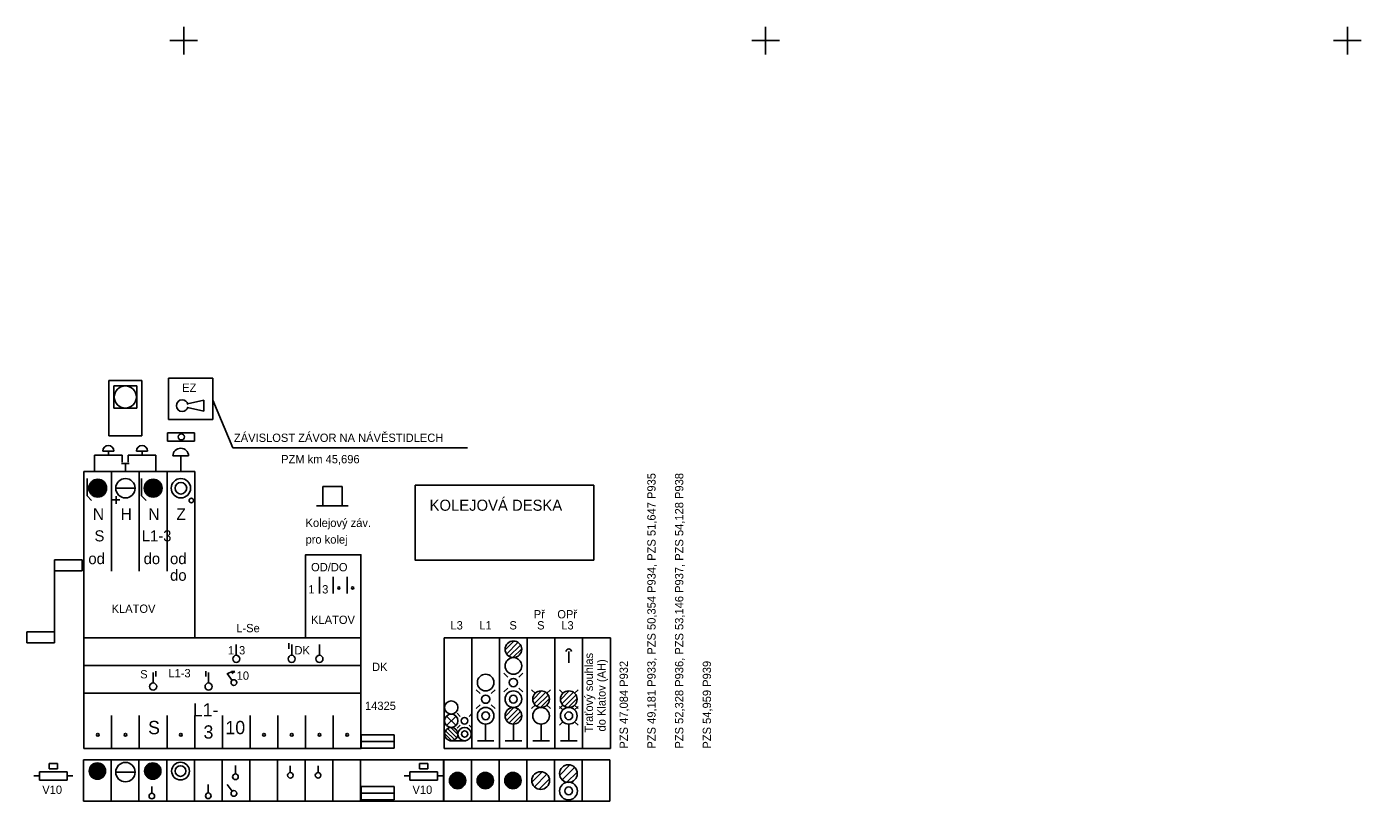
# Model space of a CAD drawing. Extents: x -28 to 822, y 61 to 665.
# Drawn here: x 340.1 to 821.8, y 385.1 to 664.7 of the extents above; entities that cross this region are included whole.
import ezdxf

# ---------------------------------------------------------------- set-up
doc = ezdxf.new("R2010")
doc.units = 0
for name, color, linetype in [('KOLEJIŠTĚ', 7, 'Continuous'), ('nové', 7, 'Continuous'), ('POPIS', 7, 'Continuous'), ('Vrstva 60', 7, 'Continuous')]:
    doc.layers.add(name, color=color, linetype=linetype)

# ---------------------------------------------------------------- blocks, each defined once
blk = doc.blocks.new('ZT18')
for p, q in [((10, 6), (0, 6)), ((0, 6), (0, 2)), ((10, 2), (10, 6)), ((0, 2), (10, 2))]:
    blk.add_line(p, q)
blk.add_lwpolyline([(0, 4), (0, 4), (10, 4)])
blk = doc.blocks.new('ZT95')
for p, q in [((2.79, 4.07), (0.93, 2.21)), ((3.63, 3.63), (1.37, 1.37)), ((4.07, 2.79), (2.21, 0.93))]:
    blk.add_line(p, q)
blk.add_circle((2.5, 2.5), 1.6)
blk = doc.blocks.new('HR6')
for p, q in [((-2.26, 0.4), (2.26, 0.4)), ((-2.2, 0.09), (2.2, 0.09)), ((-2.16, 0.8), (2.16, 0.8)), ((-1.96, 1.2), (1.96, 1.2)), ((-1.75, 1.49), (1.75, 1.49)), ((-1.56, 1.69), (1.56, 1.69)), ((-1.3, 1.89), (1.3, 1.89)), ((-0.95, 2.09), (0.95, 2.09)), ((-2.26, -0.4), (2.26, -0.4)), ((-2.2, -0.09), (2.2, -0.09)), ((-2.16, -0.8), (2.16, -0.8)), ((-1.96, -1.2), (1.96, -1.2)), ((-1.75, -1.49), (1.75, -1.49)), ((-1.56, -1.69), (1.56, -1.69)), ((-1.3, -1.89), (1.3, -1.89)), ((-0.95, -2.09), (0.95, -2.09))]:
    blk.add_line(p, q)
for start, end in [(0, 180), (180, 0)]:
    blk.add_arc((0, 0), 2.3, start, end)
blk = doc.blocks.new('ZT94')
at = {"xscale": 0.6400000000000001, "yscale": 0.6400000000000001}
blk.add_blockref('HR6', (2.5, 2.5), dxfattribs=at)
blk = doc.blocks.new('ZT87')
for start, end in [(0, 180), (180, 0)]:
    blk.add_arc((2.5, 2.5), 0.25, start, end)
blk = doc.blocks.new('ZT54')
for p, q in [((4.71, 6.11), (5.58, 5.6)), ((4.73, 6.09), (5.71, 6.11)), ((5.48, 3.64), (6.92, 5.56))]:
    blk.add_line(p, q)
blk.add_circle((5, 3), 0.8)
blk.add_arc((4.55, 1.46), 4.63, 60.0691, 87.3254)
blk = doc.blocks.new('HR1')
blk.add_line((-2.5, 0), (2.5, 0))
blk.add_circle((0, 0), 2.5)
blk = doc.blocks.new('ZT75')
at = {"xscale": 0.8, "yscale": 0.8000000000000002}
blk.add_blockref('HR6', (0, 0), dxfattribs=at)
blk = doc.blocks.new('HR3')
for radius in [2.5, 1.5]:
    blk.add_circle((0, 0), radius)
blk = doc.blocks.new('ZT72')
at = {"xscale": 0.8, "yscale": 0.8000000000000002}
blk.add_blockref('HR3', (0, 0), dxfattribs=at)
blk = doc.blocks.new('ZT41')
blk.add_line((5, 10.8), (5, 13.2))
blk.add_circle((5, 10), 0.8)
blk = doc.blocks.new('ZT11')
for p, q in [((-5, 7.5), (-5, 5.5)), ((-5, 7.5), (0, 7.5)), ((0, 7.5), (0, -7.5)), ((-5, 5.5), (0, 5.5)), ((5, -5.5), (0, -5.5)), ((5, -7.5), (5, -5.5)), ((0, -7.5), (5, -7.5))]:
    blk.add_line(p, q)
blk = doc.blocks.new('ZT44')
blk.add_line((5, 3.8), (5, 6.2))
blk.add_circle((5, 3), 0.8)
blk = doc.blocks.new('ZN4')
for p, q in [((-1, 0), (1, 0)), ((0, 1), (0, -1))]:
    blk.add_line(p, q)
blk = doc.blocks.new('ZT17')
for p, q in [((-2.5, 5), (2.5, 5)), ((-2.5, 0), (-2.5, 5)), ((2.5, 5), (2.5, 0)), ((-4.0625, 0), (4.0625, 0))]:
    blk.add_line(p, q)
blk = doc.blocks.new('HR')
for p, q in [((-3.54, 10.21), (-3.54, 0.21)), ((2.46, 10.21), (-3.54, 10.21)), ((2.46, 0.21), (2.46, 10.21)), ((-3.54, 0.21), (2.46, 0.21))]:
    blk.add_line(p, q)
blk.add_circle((-0.54, 7.21), 2)
at = {"layer": 'KOLEJIŠTĚ'}
for p, q in [((-2.59, 5.2), (-2.59, 9.25)), ((-2.59, 9.25), (1.51, 9.25)), ((1.51, 9.25), (1.51, 5.2)), ((1.51, 5.2), (-2.59, 5.2))]:
    blk.add_line(p, q, dxfattribs=at)
blk = doc.blocks.new('SB1')
for p, q in [((0, 1.08), (-1, 1.08)), ((1, 1.08), (0, 1.08)), ((0, 1.08), (0, -1.08))]:
    blk.add_line(p, q)
blk = doc.blocks.new('KD5')
for p, q in [((-2, 4), (2, 4)), ((0, 4), (0, 0))]:
    blk.add_line(p, q)
blk.add_arc((0, 4), 2, 0, 180)
blk = doc.blocks.new('ZT12')
blk.add_blockref('KD5', (0, 0))
blk = doc.blocks.new('KD15')
for p, q in [((-1.5, -6), (-0.5, -1.5)), ((0.5, -1.5), (1.5, -6)), ((-1.5, -6), (1.5, -6))]:
    blk.add_line(p, q)
for start, end in [(0, 180), (0, 180), (0, 180), (0, 180), (0, 180), (0, 180), (180, 257.0613), (282.9188, 360), (282.9188, 360), (282.9188, 360), (282.9188, 360), (282.9188, 360), (281.7695, 0)]:
    blk.add_arc((0, 0), 1.63, start, end)

msp = doc.modelspace()

# ---------------------------------------------------------------- linework, layer by layer
for p, q in [((371.62, 511.53), (367.62, 511.53)), ((369.62, 511.53), (369.62, 510.03)), ((379.78, 511.53), (383.78, 511.53)), ((381.78, 511.53), (381.78, 510.03)), ((374.62, 510.03), (364.62, 510.03)), ((364.62, 510.03), (364.62, 504.2)), ((374.62, 507.53), (374.62, 510.03)), ((376.78, 507.53), (376.78, 510.03)), ((376.78, 510.03), (386.78, 510.03)), ((386.78, 510.03), (386.78, 504.2)), ((361.92, 501.63), (361.92, 495.34)), ((381.61, 501.63), (381.61, 495.34)), ((361.92, 495.34), (363.55, 493.71)), ((381.61, 495.34), (383.23, 493.71)), ((515.98, 442.98), (512.78, 439.78)), ((517.38, 442.38), (513.38, 438.38)), ((518.38, 441.48), (514.18, 437.38)), ((518.78, 440.18), (515.58, 436.98)), ((535.78, 439.14), (535.78, 435.14)), ((513.78, 429.98), (512.38, 431.38)), ((517.78, 429.98), (519.18, 431.38)), ((503.78, 423.98), (502.38, 425.38)), ((507.78, 423.98), (509.18, 425.38)), ((513.78, 425.98), (512.38, 424.58)), ((517.78, 425.98), (519.18, 424.58)), ((523.78, 423.98), (522.38, 425.38)), ((525.98, 424.98), (522.78, 421.78)), ((527.38, 424.38), (523.38, 420.38)), ((527.78, 423.98), (529.18, 425.38)), ((533.78, 423.98), (532.38, 425.38)), ((535.98, 424.98), (532.78, 421.78)), ((537.38, 424.38), (533.38, 420.38)), ((537.78, 423.98), (539.18, 425.38)), ((503.78, 419.98), (502.38, 418.58)), ((507.78, 419.98), (509.18, 418.58)), ((523.78, 419.98), (522.38, 418.58)), ((528.38, 423.48), (524.18, 419.38)), ((528.78, 422.18), (525.58, 418.98)), ((527.78, 419.98), (529.18, 418.58)), ((533.78, 419.98), (532.38, 418.58)), ((533.78, 417.98), (532.38, 419.38)), ((538.38, 423.48), (534.18, 419.38)), ((538.78, 422.18), (535.58, 418.98)), ((537.78, 419.98), (539.18, 418.58)), ((537.78, 417.98), (539.18, 419.38)), ((494.98, 412.58), (491.78, 415.78)), ((494.98, 415.78), (491.78, 412.58)), ((496.58, 415.78), (495.46, 416.9)), ((499.78, 415.78), (500.9, 416.9)), ((515.98, 418.98), (512.78, 415.78)), ((517.38, 418.38), (513.38, 414.38)), ((518.38, 417.48), (514.18, 413.38)), ((518.78, 416.18), (515.58, 412.98)), ((490.98, 409.54), (493.54, 406.98)), ((491.3, 410.58), (494.66, 407.3)), ((492.1, 411.3), (495.3, 408.1)), ((493.22, 411.78), (495.78, 409.22)), ((496.58, 412.58), (495.46, 411.46)), ((499.78, 412.58), (500.9, 411.46)), ((505.78, 412.98), (505.78, 406.98)), ((515.78, 412.98), (515.78, 406.98)), ((525.78, 412.98), (525.78, 406.98)), ((533.78, 413.98), (532.38, 412.58)), ((535.78, 412.98), (535.78, 406.98)), ((537.78, 413.98), (539.18, 412.58)), ((492.78, 406.98), (498.78, 406.98)), ((502.78, 406.98), (508.78, 406.98)), ((512.78, 406.98), (518.78, 406.98)), ((522.78, 406.98), (528.78, 406.98)), ((532.78, 406.98), (538.78, 406.98)), ((360.62, 400.11), (360.62, 385.11)), ((460.62, 400.11), (460.62, 385.11)), ((490.62, 400.11), (490.62, 385.11)), ((354.76, 395.79), (344.76, 395.79)), ((344.76, 395.79), (344.76, 392.79)), ((354.76, 392.79), (354.76, 395.79)), ((435.28, 395.44), (435.28, 397.97)), ((445.28, 395.44), (445.28, 397.97)), ((478.37, 395.79), (478.37, 392.79)), ((488.37, 395.79), (478.37, 395.79)), ((488.37, 392.79), (488.37, 395.79)), ((342.76, 394.29), (344.76, 394.29)), ((344.76, 392.79), (354.76, 392.79)), ((354.76, 394.29), (356.76, 394.29)), ((385.28, 387.94), (385.28, 390.47)), ((414.31, 388.78), (412.47, 391.24)), ((476.37, 394.29), (478.37, 394.29)), ((478.37, 392.79), (488.37, 392.79)), ((488.37, 394.29), (490.37, 394.29))]:
    msp.add_line(p, q)
for centre, radius in [((399.56, 493.71), 0.811), ((515.78, 439.98), 3), ((515.78, 433.98), 3), ((505.78, 427.98), 3), ((515.78, 421.98), 3), ((525.78, 421.98), 3), ((535.78, 421.98), 3), ((493.38, 418.98), 2.4), ((515.78, 421.98), 1.4), ((493.38, 414.18), 2.4), ((505.78, 415.98), 3), ((505.78, 415.98), 1.4), ((515.78, 415.98), 3), ((525.78, 415.98), 3), ((535.78, 415.98), 3), ((535.78, 415.98), 1.4), ((493.38, 409.38), 2.4), ((498.18, 409.38), 2.4), ((498.18, 409.38), 1.12), ((435.31, 394.5), 1), ((445.31, 394.5), 1), ((535.68, 388.84), 3.2), ((535.76, 388.89), 1.4), ((385.31, 387), 1), ((414.93, 387.96), 1.02)]:
    msp.add_circle(centre, radius)
for centre, radius, start, end in [((369.62, 511.53), 2, 0, 180), ((381.78, 511.53), 2, 0, 180), ((535.78, 439.14), 1, 0, 180), ((515.78, 427.98), 1.5, 0, 180), ((515.78, 427.98), 1.5, 180, 0), ((505.78, 421.98), 1.5, 0, 180), ((505.78, 421.98), 1.5, 180, 0), ((498.18, 414.18), 1.2, 0, 180), ((498.18, 414.18), 1.2, 180, 0)]:
    msp.add_arc(centre, radius, start, end)
at = {"layer": 'KOLEJIŠTĚ'}
for p, q in [((391.26, 537.91), (407.26, 537.91)), ((391.26, 522.91), (391.26, 537.91)), ((407.26, 537.91), (407.26, 522.91)), ((414.58, 512.74), (407.26, 529.91)), ((407.26, 522.91), (391.26, 522.91)), ((390.99, 518.17), (400.74, 518.17)), ((390.99, 515.07), (390.99, 518.17)), ((400.74, 518.17), (400.74, 515.07)), ((400.74, 515.07), (390.99, 515.07)), ((414.58, 512.74), (499.26, 512.74)), ((370.78, 504.14), (370.78, 468.14)), ((380.78, 468.14), (380.78, 504.14)), ((380.78, 504.14), (390.78, 504.14)), ((390.78, 504.14), (390.78, 468.14)), ((445.78, 466.14), (445.78, 460.14)), ((450.78, 466.14), (450.78, 460.14)), ((455.78, 466.14), (455.78, 460.14)), ((360.78, 444.14), (460.78, 444.14)), ((360.78, 434.14), (360.78, 444.14)), ((490.78, 444.14), (540.78, 444.14)), ((490.78, 404.14), (490.78, 444.14)), ((490.78, 444.14), (490.78, 404.14)), ((500.78, 404.14), (500.78, 444.14)), ((500.78, 444.14), (510.78, 444.14)), ((510.78, 444.14), (510.78, 404.14)), ((520.78, 444.14), (520.78, 404.14)), ((530.78, 404.14), (530.78, 444.14)), ((434.78, 440.14), (434.78, 442.14)), ((460.78, 434.14), (360.78, 434.14)), ((460.78, 424.14), (460.78, 434.14)), ((386.78, 430.14), (386.78, 432.14)), ((404.78, 432.14), (404.78, 430.14)), ((360.78, 424.14), (460.78, 424.14)), ((360.78, 404.14), (360.78, 424.14)), ((370.78, 416.14), (370.78, 404.14)), ((380.78, 416.14), (380.78, 404.14)), ((390.78, 416.14), (390.78, 404.14)), ((400.78, 416.14), (400.78, 404.14)), ((410.78, 416.14), (410.78, 404.14)), ((420.78, 416.14), (420.78, 404.14)), ((430.78, 416.14), (430.78, 404.14)), ((440.78, 416.14), (440.78, 404.14)), ((450.78, 416.14), (450.78, 404.14)), ((540.66, 400.11), (360.62, 400.11)), ((360.62, 400.11), (391.49, 400.11)), ((360.64, 400.11), (360.64, 385.11)), ((370.66, 400.11), (370.66, 385.11)), ((380.62, 400.11), (550.62, 400.11)), ((380.66, 385.11), (380.66, 400.11)), ((390.66, 400.11), (390.66, 385.11)), ((400.66, 385.11), (400.66, 400.11)), ((401.49, 400.11), (412.49, 400.11)), ((410.66, 400.11), (410.66, 385.11)), ((412.49, 400.11), (411.49, 400.11)), ((420.66, 385.11), (420.66, 400.11)), ((421.49, 400.11), (431.49, 400.11)), ((430.66, 400.11), (430.66, 385.11)), ((440.66, 385.11), (440.66, 400.11)), ((441.49, 400.11), (451.49, 400.11)), ((450.66, 400.11), (450.66, 385.11)), ((460.66, 385.11), (460.66, 400.11)), ((461.49, 400.11), (471.49, 400.11)), ((490.66, 400.11), (490.66, 385.11)), ((490.78, 404.14), (500.78, 404.14)), ((500.66, 385.11), (500.66, 400.11)), ((500.78, 404.14), (510.78, 404.14)), ((501.49, 400.11), (511.49, 400.11)), ((510.66, 400.11), (510.66, 385.11)), ((510.78, 404.14), (520.78, 404.14)), ((520.66, 385.11), (520.66, 400.11)), ((520.78, 404.14), (530.78, 404.14)), ((530.66, 400.11), (530.66, 385.11)), ((530.78, 404.14), (540.78, 404.14)), ((348.26, 398.79), (351.26, 398.79)), ((348.26, 396.79), (348.26, 398.79)), ((351.26, 396.79), (348.26, 396.79)), ((351.26, 398.79), (351.26, 396.79)), ((481.87, 396.79), (481.87, 398.79)), ((481.87, 398.79), (484.87, 398.79)), ((484.87, 396.79), (481.87, 396.79)), ((484.87, 398.79), (484.87, 396.79)), ((520.66, 385.11), (360.62, 385.11)), ((540.66, 385.11), (380.62, 385.11)), ((491.49, 385.11), (501.49, 385.11))]:
    msp.add_line(p, q, dxfattribs=at)
msp.add_lwpolyline([(360.78, 404.14), (460.78, 404.14), (460.78, 474.14), (440.78, 474.14), (440.78, 444.14), (400.78, 444.14), (400.78, 504.14), (360.78, 504.14), (360.78, 404.14)], dxfattribs=at)
msp.add_circle((395.97, 516.67), 1.11, dxfattribs=at)
at = {"layer": 'nové'}
for p, q in [((540.78, 444.14), (540.78, 404.14)), ((540.78, 444.14), (550.78, 444.14)), ((550.78, 444.14), (550.78, 404.14)), ((540.66, 400.11), (540.66, 385.11)), ((550.62, 400.11), (540.66, 400.11)), ((540.78, 404.14), (550.78, 404.14)), ((550.62, 400.11), (550.62, 385.11)), ((550.62, 400.11), (550.62, 385.11)), ((550.62, 385.11), (540.66, 385.11))]:
    msp.add_line(p, q, dxfattribs=at)
at = {"layer": 'POPIS'}
msp.add_lwpolyline([(480.33, 499.19), (480.33, 472.2), (544.78, 472.2), (544.78, 499.19)], close=True, dxfattribs=at)
at = {"layer": 'Vrstva 60'}
for p, q in [((396.81, 654.73), (396.81, 664.73)), ((606.81, 654.73), (606.81, 664.73)), ((816.81, 654.73), (816.81, 664.73)), ((391.81, 659.73), (401.81, 659.73)), ((601.81, 659.73), (611.81, 659.73)), ((811.81, 659.73), (821.81, 659.73))]:
    msp.add_line(p, q, dxfattribs=at)

# ---------------------------------------------------------------- block references
at = {"xscale": 1.4000000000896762, "yscale": 1.4000000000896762}
for name, p in [('HR6', (365.78, 498.14)), ('HR1', (375.78, 498.14)), ('HR6', (385.78, 498.14)), ('HR3', (395.78, 498.14)), ('ZN4', (372.41, 493.92)), ('HR1', (375.78, 395.64))]:
    msp.add_blockref(name, p, dxfattribs=at)
at = {"layer": 'KOLEJIŠTĚ'}
for name, p, xscale, yscale in [('HR', (376.81, 516.63), 2, 2), ('ZT12', (395.74, 504.16), 1.4000000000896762, 1.4000000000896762), ('SB1', (375.78, 505.54), 1.4000000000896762, 1.4000000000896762), ('ZT17', (450.46, 491.74), 1.4000000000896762, 1.4000000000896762), ('ZT87', (448.78, 458.14), 1.6000000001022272, 1.6000000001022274), ('ZT87', (453.78, 458.14), 1.6000000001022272, 1.6000000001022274), ('ZT44', (407.78, 431.74), 1.6000000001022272, 1.6000000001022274), ('ZT44', (427.78, 431.74), 1.6000000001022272, 1.6000000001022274), ('ZT44', (437.78, 431.74), 1.6000000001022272, 1.6000000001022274), ('ZT44', (377.78, 421.74), 1.6000000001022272, 1.6000000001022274), ('ZT44', (397.78, 421.74), 1.6000000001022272, 1.6000000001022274), ('ZT87', (360.78, 404.14), 2, 2), ('ZT87', (370.78, 404.14), 2, 2), ('ZT87', (390.78, 404.14), 2, 2), ('ZT87', (420.78, 404.14), 2, 2), ('ZT87', (430.78, 404.14), 2, 2), ('ZT87', (440.78, 404.14), 2, 2), ('ZT87', (450.78, 404.14), 2, 2), ('ZT18', (460.8, 401.88), 1.2000000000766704, 1.2000000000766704), ('ZT75', (365.66, 396.03), 1.600000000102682, 1.600000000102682), ('ZT75', (385.66, 396.03), 1.600000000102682, 1.600000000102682), ('ZT72', (395.66, 396.03), 1.600000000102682, 1.600000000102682), ('ZT41', (409.08, 381.16), 1.2800000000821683, 1.2800000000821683), ('ZT94', (490.64, 387.61), 2, 2), ('ZT94', (500.64, 387.61), 2, 2), ('ZT94', (510.64, 387.61), 2, 2), ('ZT95', (520.64, 387.61), 2, 2), ('ZT95', (530.64, 390.11), 2, 2), ('ZT41', (399.29, 374.31), 1.2800000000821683, 1.2800000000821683), ('ZT18', (460.8, 383.3), 1.2000000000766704, 1.2000000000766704)]:
    msp.add_blockref(name, p, dxfattribs=dict(at, xscale=xscale, yscale=yscale))
for name, p, xscale, yscale, rotation in [('KD15', (396.26, 527.91), 1.2960000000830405, 1.2960000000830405, 90), ('ZT11', (350.14, 457.31), 2, -2, 180), ('ZT54', (421.33, 424.12), 1.2800000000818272, -1.2800000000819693, 180)]:
    msp.add_blockref(name, p, dxfattribs=dict(at, xscale=xscale, yscale=yscale, rotation=rotation))

# ---------------------------------------------------------------- texts
for s, height, p in [('N', 4.2, (364.02, 486.71)), ('H', 4.2, (374.02, 486.71)), ('N', 4.2, (384.02, 486.71)), ('Z', 4.2, (394.18, 486.71)), ('L1-', 4.8, (400.11, 415.74)), ('S', 4.8, (383.95, 409.34)), ('3', 4.8, (403.95, 407.74)), ('10', 4.8, (411.85, 409.34))]:
    msp.add_text(s, height=height).set_placement(p)
for s, height, p in [('EZ', 3, (396.26, 532.91)), ('ZÁVISLOST ZÁVOR NA NÁVĚSTIDLECH', 3, (414.94, 514.84)), ('PZM km 45,696', 3, (431.98, 507.12)), ('Kolejový záv.', 3, (440.78, 484.14)), ('S', 4, (364.61, 478.94)), ('L1-3', 4, (381.68, 478.94)), ('pro kolej', 3, (440.78, 478.14)), ('od', 4, (362.4, 470.72)), ('do', 4, (382.34, 470.72)), ('od', 4, (391.87, 470.72)), ('do', 4, (391.89, 464.73)), ('OD/DO', 3, (442.78, 468.14)), ('1', 3, (441.78, 460.14)), ('3', 3, (446.78, 460.14)), ('KLATOV', 3, (370.78, 453.14)), ('Př', 3, (523.14, 451.14)), ('OPř', 3, (531.64, 451.14)), ('L-Se', 3, (415.78, 446.14)), ('KLATOV', 3, (442.78, 449.14)), ('L3', 3, (493.07, 447.14)), ('L1', 3, (503.5, 447.14)), ('S', 3, (514.35, 447.14)), ('S', 3, (524.35, 447.14)), ('L3', 3, (533.07, 447.14)), ('1', 3, (412.78, 438.14)), ('3', 3, (416.78, 438.14)), ('DK', 3, (436.78, 438.14)), ('DK', 3, (464.78, 432.14)), ('S', 3, (381.1, 429.49)), ('L1-3', 3, (391.28, 429.87)), ('10', 3, (415.92, 428.99)), ('14325', 3, (462.24, 418.09))]:
    msp.add_text(s, height=height, dxfattribs=at).set_placement(p)
at = {"layer": 'nové'}
for s, p in [('PZS 49,181 P933, PZS 50,354 P934, PZS 51,647 P935', (567.12, 404.14)), ('PZS 52,328 P936, PZS 53,146 P937, PZS 54,128 P938', (577.12, 404.14)), ('Traťový souhlas', (544.5, 409.97)), ('do Klatov (AH)', (549.07, 410.31)), ('PZS 47,084 P932', (557.12, 404.14)), ('PZS 54,959 P939', (587.12, 404.14))]:
    msp.add_text(s, height=3, rotation=90, dxfattribs=at).set_placement(p)
for p in [(345.76, 387.79), (479.37, 387.79)]:
    msp.add_text('V10', height=3, dxfattribs=at).set_placement(p)
at = {"layer": 'POPIS'}
msp.add_text('KOLEJOVÁ DESKA', height=4, dxfattribs=at).set_placement((485.55, 489.99))

doc.saveas('drawing.dxf')
